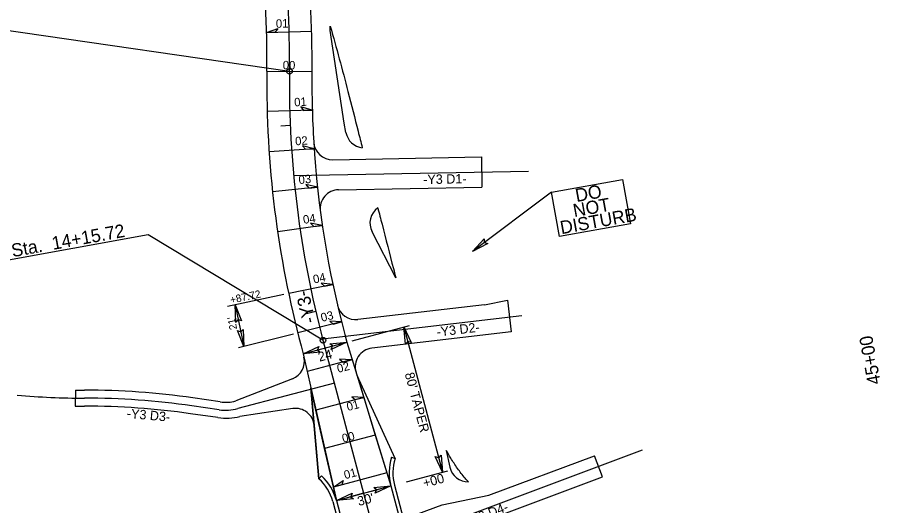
# Model space of a CAD drawing. Extents: x 1616561 to 1622460, y 896726 to 899651.
# Drawn here: x 1620740.5 to 1621199.2, y 898221.3 to 898481.3 of the extents above; entities that cross this region are included whole.
import ezdxf

# ---------------------------------------------------------------- set-up
doc = ezdxf.new("R2010")
doc.units = 0
for name, color, linetype in [('Prop Dimension', 7, 'Continuous'), ('Prop DSN Text', 7, 'Continuous'), ('Prop Horizontal Alignment', 7, 'Continuous'), ('Prop Horizontal Alignment Tick Small', 7, 'Continuous'), ('Prop North Arrow NAD83 for Plan Sheets CELL', 7, 'Continuous'), ('Prop Rem of Exist Asph Pvmt', 7, 'Continuous'), ('Prop Shade Light', 7, 'Continuous'), ('Prop Superelevation  Arrow CELL', 7, 'Continuous'), ('Prop Superelevation Label', 7, 'Continuous'), ('Prop Terminator CELL', 7, 'Continuous'), ('Scratch_Level_1', 7, 'Continuous'), ('Sheet Cutting Line CELL', 7, 'Continuous'), ('Sheet North Arrow CELL', 7, 'Continuous'), ('Sheet Sticker Preliminary CELL', 7, 'Continuous')]:
    doc.layers.add(name, color=color, linetype=linetype)

msp = doc.modelspace()

# ---------------------------------------------------------------- linework, layer by layer
at = {"layer": 'Prop Dimension'}
for p, q in [((1620918.65, 898309.15), (1620949.04, 898317.22)), ((1620946.14, 898316.45), (1620966.67, 898239.13)), ((1620892.56, 898302.22), (1620915.75, 898308.38)), ((1620947.5, 898234.03), (1620969.57, 898239.9)), ((1620910.19, 898224.13), (1620939.19, 898231.83)), ((1620925.13, 898226.32), (1620925.13, 898226.32))]:
    msp.add_line(p, q, dxfattribs=at)
at = {"layer": 'Prop DSN Text'}
msp.add_line((1621024.63, 898388.2), (1620982.54, 898356.71), dxfattribs=at)
msp.add_lwpolyline([(1621024.63, 898388.2), (1621062.35, 898395.02), (1621066.63, 898371.37), (1621028.91, 898364.54)], close=True, dxfattribs=at)
at = {"layer": 'Prop Horizontal Alignment'}
for p, q in [((1620941.51, 898246.48), (1620921.19, 898290.62)), ((1620900.91, 898235.7), (1620896.65, 898284.08)), ((1620939.6, 898247.1), (1620941.51, 898246.48)), ((1620902.26, 898237.18), (1620900.91, 898235.7))]:
    msp.add_line(p, q, dxfattribs=at)
for centre, start, end in [((1620965.28, 898238.76), 162.0128, 194.8727), ((1620884.1, 898217.2), 14.8727, 47.7326)]:
    msp.add_arc(centre, 27, start, end, dxfattribs=at)
at = {"layer": 'Prop Horizontal Alignment Tick Small'}
for p, q in [((1620939.6, 898247.1), (1620941.51, 898246.48)), ((1620902.26, 898237.18), (1620900.91, 898235.7)), ((1620941.12, 898232.34), (1620950.92, 898195.46)), ((1620908.26, 898223.61), (1620914.86, 898198.77))]:
    msp.add_line(p, q, dxfattribs=at)
for centre, start, end in [((1620965.28, 898238.76), 162.0128, 194.8727), ((1620884.1, 898217.2), 14.8727, 47.7326)]:
    msp.add_arc(centre, 25, start, end, dxfattribs=at)
at = {"layer": 'Prop North Arrow NAD83 for Plan Sheets CELL'}
for points in [[(1620873.08, 898473.17), (1620879.02, 898475.34), (1620877.7, 898473.3)], [(1620897.4, 898431.84), (1620891.35, 898433.67), (1620892.78, 898431.71)], [(1620898.37, 898411.34), (1620892.25, 898412.93), (1620893.76, 898411.03)], [(1620900.15, 898390.89), (1620893.97, 898392.24), (1620895.55, 898390.4)], [(1620902.73, 898370.52), (1620896.51, 898371.63), (1620898.16, 898369.85)], [(1620908.33, 898339.14), (1620902.05, 898339.86), (1620903.8, 898338.19)], [(1620912.94, 898319.14), (1620906.64, 898319.61), (1620908.46, 898318.01)], [(1620918.25, 898298.98), (1620911.94, 898299.38), (1620913.78, 898297.8)], [(1620924.75, 898278.98), (1620918.44, 898279.37), (1620920.28, 898277.79)], [(1620908.59, 898231.23), (1620913.87, 898234.71), (1620913.06, 898232.42)]]:
    msp.add_lwpolyline(points, close=True, dxfattribs=at)
at = {"layer": 'Prop Rem of Exist Asph Pvmt'}
for p, q in [((1620906.85, 898474.21), (1620906.98, 898476.52)), ((1620914.34, 898424.83), (1620906.85, 898474.21)), ((1620915.29, 898419.91), (1620914.34, 898424.83)), ((1620941.85, 898342.6), (1620929.15, 898367.09)), ((1620968.63, 898250.77), (1620970.57, 898241.91))]:
    msp.add_line(p, q, dxfattribs=at)
for centre, start, end in [((1620925.11, 898421.8), 190.9231, 263.655), ((1620938.03, 898371.7), 125.4384, 207.4081), ((1620980.34, 898244.05), 192.311, 270.5933)]:
    msp.add_arc(centre, 10, start, end, dxfattribs=at)
for points in [[(1620906.98, 898476.52), (1620916.38, 898441.77), (1620921.77, 898420.6), (1620924, 898411.86)], [(1620932.23, 898379.84), (1620934.47, 898371.18), (1620940.55, 898347.53), (1620941.85, 898342.6)], [(1620980.44, 898234.05), (1620978.7, 898235.95), (1620976.61, 898238.54), (1620974.63, 898241.19), (1620972.77, 898243.9), (1620971.03, 898246.7), (1620968.63, 898250.77)]]:
    msp.add_spline(points, degree=3, dxfattribs=at)
at = {"layer": 'Prop Shade Light'}
for p, q in [((1620941.51, 898246.48), (1620921.19, 898290.62)), ((1620939.6, 898247.1), (1620941.51, 898246.48)), ((1620900.91, 898235.7), (1620902.26, 898237.18))]:
    msp.add_line(p, q, dxfattribs=at)
for points in [[(1620921.19, 898290.62), (1620924.75, 898278.98), (1620930.9, 898258.89), (1620937.06, 898238.79), (1620939.19, 898231.83)], [(1620910.19, 898224.13), (1620908.59, 898231.23), (1620903.96, 898251.73), (1620899.33, 898272.23), (1620896.65, 898284.08)], [(1620896.65, 898284.08), (1620898.42, 898264.01), (1620900.91, 898235.7)]]:
    msp.add_lwpolyline(points, dxfattribs=at)
for centre, start, end in [((1620965.28, 898238.76), 162.0128, 194.8727), ((1620884.1, 898217.2), 14.8727, 47.7326)]:
    msp.add_arc(centre, 27, start, end, dxfattribs=at)
at = {"layer": 'Prop Superelevation  Arrow CELL'}
for p, q in [((1620885.68, 898423.61), (1620880.69, 898423.4)), ((1620899.25, 898324.68), (1620894.38, 898323.54))]:
    msp.add_line(p, q, dxfattribs=at)
at = {"layer": 'Prop Superelevation Label'}
for q in [(1620932.42, 898230.03), (1620916.96, 898225.92)]:
    msp.add_line((1620924.69, 898227.98), q, dxfattribs=at)
at = {"layer": 'Prop Terminator CELL'}
for p, q in [((1620908.33, 898405.42), (1620987.31, 898406.94)), ((1620987.31, 898406.94), (1620987.62, 898390.94)), ((1620911.39, 898389.47), (1620987.62, 898390.94)), ((1620989.02, 898328.31), (1621001.15, 898330.66)), ((1621001.15, 898330.66), (1621003.12, 898313.85)), ((1620989.02, 898328.31), (1620921.68, 898320.43)), ((1620914.66, 898312.51), (1620915.75, 898308.38)), ((1621003.12, 898313.85), (1620929.07, 898305.18)), ((1620915.75, 898308.38), (1620939.19, 898231.83)), ((1620891.46, 898306.35), (1620892.56, 898302.22)), ((1620892.56, 898302.22), (1620910.19, 898224.13)), ((1620886.86, 898288.87), (1620856.72, 898277.09)), ((1620771.38, 898282.86), (1620771.28, 898274.36)), ((1620848.43, 898276.61), (1620833.86, 898278.71)), ((1620887, 898273.03), (1620858.9, 898268.88)), ((1620847.22, 898268.2), (1620832.65, 898270.29)), ((1620991.29, 898226.9), (1621047.48, 898247.93)), ((1621051.69, 898236.7), (1621047.48, 898247.93)), ((1620952.89, 898199.71), (1621051.69, 898236.7)), ((1620939.19, 898231.83), (1620948.98, 898194.94)), ((1620966.48, 898221.88), (1620991.29, 898226.9)), ((1620910.19, 898224.13), (1620916.79, 898199.28)), ((1620948.77, 898215.25), (1620966.48, 898221.88))]:
    msp.add_line(p, q, dxfattribs=at)
for points in [[(1620990.68, 898360.86), (1620982.54, 898356.71), (1620988.83, 898363.41), (1620988.87, 898361.44)], [(1620856.64, 898319.08), (1620856.31, 898328.21), (1620859.73, 898319.68), (1620857.93, 898320.48)], [(1620860.63, 898315.19), (1620860.96, 898306.06), (1620857.53, 898314.59), (1620859.33, 898313.79)], [(1620946.95, 898307.35), (1620946.14, 898316.45), (1620950.01, 898308.11), (1620948.16, 898308.81)], [(1620906.66, 898307.57), (1620915.75, 898308.38), (1620907.42, 898304.51), (1620908.12, 898306.35)], [(1620901.66, 898303.03), (1620892.56, 898302.22), (1620900.9, 898306.09), (1620900.19, 898304.24)], [(1620965.86, 898248.22), (1620966.67, 898239.13), (1620962.8, 898247.46), (1620964.64, 898246.76)], [(1620930.09, 898231.02), (1620939.19, 898231.83), (1620930.85, 898227.96), (1620931.55, 898229.8)], [(1620919.29, 898224.94), (1620910.19, 898224.13), (1620918.53, 898228), (1620917.83, 898226.15)]]:
    msp.add_lwpolyline(points, close=True, dxfattribs=at)
for centre, radius, start, end in [((1620352.28, 898458.77), 545, 359.3265, 14.8727), ((1620352.28, 898458.77), 521, 359.3265, 14.8727), ((1621418.2, 898446.24), 545, 179.3265, 194.8727), ((1621418.2, 898446.24), 521, 179.3265, 183.458), ((1621418.2, 898446.24), 521, 183.458, 194.8727), ((1620908.13, 898415.42), 10, 183.458, 271.103), ((1620911.58, 898379.48), 10, 91.103, 187.5072), ((1620920.51, 898330.36), 10, 193.107, 276.6789), ((1620930.23, 898295.25), 10, 96.6789, 197.0203), ((1620883.22, 898298.18), 10, 291.3381, 12.7251), ((1620776.25, 898678.58), 395.75, 269.2943, 270), ((1620776.25, 897878.58), 404.25, 81.807, 90), ((1620851.39, 898297.15), 20.75, 261.807, 284.8727), ((1620776.25, 898678.58), 404.25, 269.2943, 270), ((1620776.25, 897878.58), 395.75, 81.807, 90), ((1620888.46, 898263.14), 10, 5.0293, 98.4073), ((1620851.39, 898297.15), 29.25, 261.807, 284.8727)]:
    msp.add_arc(centre, radius, start, end, dxfattribs=at)
at = {"layer": 'Sheet Cutting Line CELL'}
for p, q in [((1620887.48, 898397.02), (1621012.46, 898399.42)), ((1620902.86, 898310.17), (1621008.85, 898322.58)), ((1620903.06, 898309.43), (1620954.2, 898116.85)), ((1620909.12, 898286.61), (1620857.81, 898272.99)), ((1620847.83, 898272.4), (1620833.26, 898274.5)), ((1620932.52, 898198.49), (1621073, 898251.08))]:
    msp.add_line(p, q, dxfattribs=at)
for centre, radius, start, end in [((1620352.28, 898458.77), 533, 359.3265, 14.8727), ((1621418.2, 898446.24), 533, 179.3265, 194.8727), ((1620776.25, 898678.58), 400, 264.8669, 270), ((1620776.25, 897878.58), 400, 81.807, 90), ((1620851.39, 898297.15), 25, 261.807, 284.8727)]:
    msp.add_arc(centre, radius, start, end, dxfattribs=at)
at = {"layer": 'Sheet North Arrow CELL'}
for p, q in [((1620885.24, 898452.5), (1620730.97, 898474.73)), ((1620810.13, 898365.53), (1620704.88, 898346.47)), ((1620903.06, 898309.43), (1620810.13, 898365.53))]:
    msp.add_line(p, q, dxfattribs=at)
for centre in [(1620885.24, 898452.5), (1620903.06, 898309.43)]:
    msp.add_circle(centre, 1.5, dxfattribs=at)
at = {"layer": 'Sheet Sticker Preliminary CELL'}
for p, q in [((1620873.08, 898473.17), (1620897.07, 898473.83)), ((1620873.24, 898452.64), (1620897.24, 898452.36)), ((1620897.4, 898431.84), (1620873.41, 898431.18)), ((1620898.37, 898411.34), (1620874.43, 898409.73)), ((1620900.15, 898390.89), (1620876.29, 898388.34)), ((1620902.73, 898370.52), (1620878.99, 898367.04)), ((1620908.33, 898339.14), (1620884.84, 898334.21)), ((1620882.24, 898333.66), (1620852.3, 898327.37)), ((1620856.31, 898328.21), (1620860.96, 898306.06)), ((1620912.94, 898319.14), (1620889.67, 898313.28)), ((1620887.37, 898312.7), (1620858.06, 898305.33)), ((1620918.6, 898299.08), (1620894.7, 898292.73)), ((1620924.75, 898278.98), (1620899.33, 898272.23)), ((1620930.9, 898258.89), (1620903.96, 898251.73)), ((1620937.06, 898238.79), (1620908.59, 898231.23))]:
    msp.add_line(p, q, dxfattribs=at)

# ---------------------------------------------------------------- texts
at = {"layer": 'Prop Dimension'}
for s, height, rotation, p in [('45+00', 7, 100.2599, (1621199.79, 898286.43)), ("24'", 5, 14.8727, (1620901.21, 898297.96)), ("80' TAPER", 5, 284.8727, (1620946.52, 898291.56)), ('+00', 5, 14.8727, (1620957.03, 898230.87)), ("30'", 5, 14.8727, (1620922.12, 898221.14))]:
    msp.add_text(s, height=height, rotation=rotation, dxfattribs=at).set_placement(p)
at = {"layer": 'Prop DSN Text'}
for s, p in [('DO', (1621037.96, 898382.92)), ('NOT', (1621036.75, 898374.87)), ('DISTURB', (1621029.88, 898365.8))]:
    msp.add_text(s, height=7, rotation=10.2599, dxfattribs=at).set_placement(p)
at = {"layer": 'Scratch_Level_1'}
for s, rotation, p in [('-Y3 D1-', 1.103, (1620956.43, 898392.47)), ('-Y3 D2-', 6.6789, (1620963.78, 898311.3)), ('-Y3 D3-', 354.9196, (1620798.61, 898268.08)), ('-Y3 D4-', 20.5237, (1620980.56, 898210.65))]:
    msp.add_text(s, height=5, rotation=rotation, dxfattribs=at).set_placement(p)
at = {"layer": 'Sheet North Arrow CELL'}
for s, rotation, p in [('-Y3- PT Sta.  14+15.72', 10.2599, (1620703.71, 898347.37)), ('-Y3-', 103.2005, (1620899.25, 898319.25))]:
    msp.add_text(s, height=7, rotation=rotation, dxfattribs=at).set_placement(p)
at = {"layer": 'Sheet Sticker Preliminary CELL'}
for s, height, rotation, p in [('01', 4.5, 1.5841, (1620878.07, 898475.65)), ('00', 4.5, 359.3265, (1620881.65, 898453.59)), ('01', 4.5, 3.8412, (1620887.91, 898433.78)), ('02', 4.5, 3.8412, (1620888.41, 898413.1)), ('03', 4.5, 6.0987, (1620890.33, 898392.46)), ('04', 4.5, 8.3561, (1620892.81, 898371.31)), ('04', 4.5, 11.8626, (1620898.3, 898339.55)), ('+87.72', 4, 11.8626, (1620854.11, 898328.83)), ("21'", 4, 101.8626, (1620857.44, 898315.41)), ('03', 4.5, 14.1201, (1620902.53, 898319.14)), ('02', 4.5, 14.8727, (1620911.16, 898292)), ('01', 4.5, 14.8727, (1620916.32, 898271.66)), ('00', 4.5, 14.8727, (1620913.85, 898254.85)), ('01', 4.5, 14.8727, (1620914.87, 898235.4))]:
    msp.add_text(s, height=height, rotation=rotation, dxfattribs=at).set_placement(p)

doc.saveas('drawing.dxf')
